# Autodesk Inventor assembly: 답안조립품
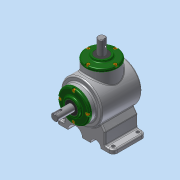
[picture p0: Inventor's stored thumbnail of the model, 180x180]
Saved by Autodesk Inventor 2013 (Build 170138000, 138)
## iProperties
Created: 2018-08
Part Number: 답안조립품
Document SubType Name: Assembly
Designer: dgall
Author: dgall
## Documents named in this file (14)
- C:\Users\dgall\Desktop\480807V1015\답안조립품.iam
- C:\Users\dgall\Desktop\480807V1015\본체.ipt
- C:\Users\dgall\Desktop\480807V1015\메인 베벨기어.ipt
- C:\Users\dgall\Desktop\480807V1015\메인 축.ipt
- 메인 축.ipt
- C:\Users\dgall\Desktop\480807V1015\베어링 6203.ipt
- C:\Users\dgall\Desktop\480807V1015\오일실 17 32 8.ipt
- C:\Users\dgall\Desktop\480807V1015\커버.ipt
- C:\Users\dgall\Desktop\480807V1015\키 5x5.ipt
- C:\Users\dgall\Desktop\480807V1015\서브 베벨기어.ipt
- C:\Users\dgall\Desktop\480807V1015\서브 축.ipt
- 서브 축.ipt
- C:\Users\dgall\Desktop\480807V1015\키 4x4.ipt
- C:\Users\dgall\Desktop\480807V1015\볼트 M4.ipt
